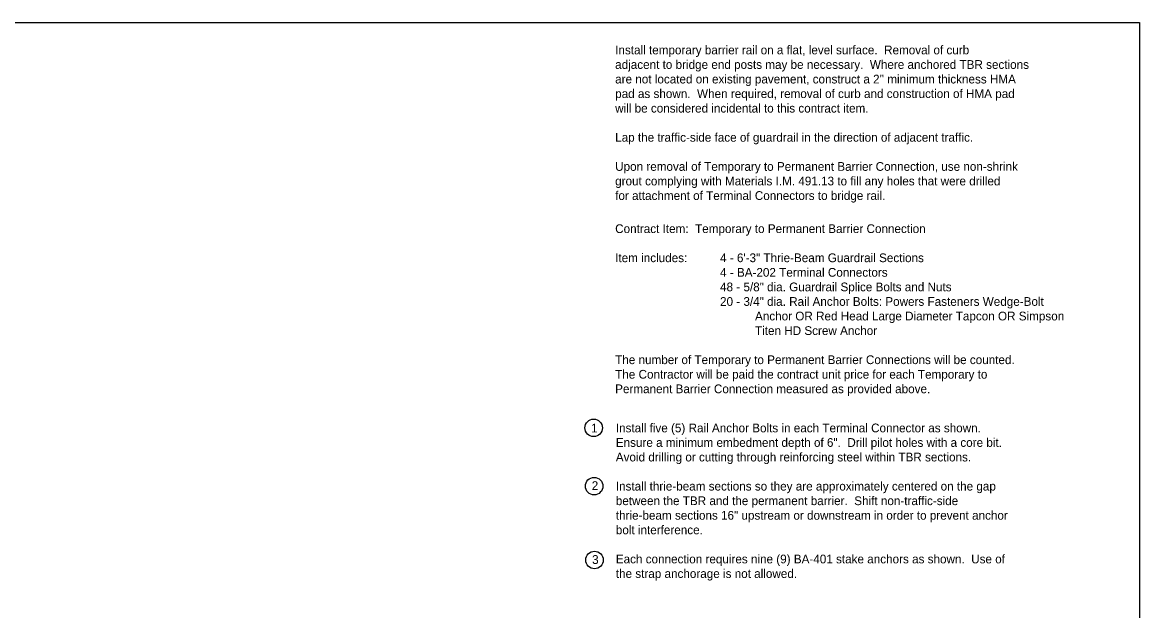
# Model space of a CAD drawing. Extents: x 10028 to 81668, y 3581 to 11018.
# Drawn here: x 14950 to 16868, y 8934 to 9944 of the extents above; entities that cross this region are included whole.
import ezdxf

# ---------------------------------------------------------------- set-up
doc = ezdxf.new("R2010")
doc.units = 0
for name, color, linetype in [('dsnTextTabulation', 7, 'Continuous'), ('Level 9', 7, 'Continuous'), ('SheetBorder', 7, 'Continuous')]:
    doc.layers.add(name, color=color, linetype=linetype)

msp = doc.modelspace()

# ---------------------------------------------------------------- linework, layer by layer
at = {"layer": 'dsnTextTabulation'}
for centre in [(15930.5, 9247.8), (15931.3, 9147.8), (15931.9, 9021)]:
    msp.add_circle(centre, 15, dxfattribs=at)
at = {"layer": 'SheetBorder'}
msp.add_lwpolyline([(13732.5, 9944), (16867.5, 9944), (16867.5, 7924), (13732.5, 7924)], close=True, dxfattribs=at)

# ---------------------------------------------------------------- texts
at = {"layer": 'dsnTextTabulation'}
for s, p in [('1', (15926.1, 9239.9)), ('2', (15927.1, 9141)), ('3', (15927.7, 9014.2))]:
    msp.add_text(s, height=15.2, dxfattribs=at).set_placement(p)
at = {"layer": 'Level 9'}
for s, p in [('Install temporary barrier rail on a flat, level surface.  Removal of curb ', (15967.4, 9889.1)), ('adjacent to bridge end posts may be necessary.  Where anchored TBR sections ', (15967.4, 9864.1)), ("are not located on existing pavement, construct a 2'' minimum thickness HMA ", (15967.4, 9839.1)), ('pad as shown.  When required, removal of curb and construction of HMA pad ', (15967.4, 9814.1)), ('will be considered incidental to this contract item.', (15967.4, 9789.1)), ('Lap the traffic-side face of guardrail in the direction of adjacent traffic.', (15967.4, 9739.1)), ('Upon removal of Temporary to Permanent Barrier Connection, use non-shrink ', (15967.4, 9689.1)), ('grout complying with Materials I.M. 491.13 to fill any holes that were drilled ', (15967.4, 9664.1)), ('for attachment of Terminal Connectors to bridge rail.', (15967.4, 9639.1)), ('Contract Item:  Temporary to Permanent Barrier Connection', (15967.4, 9582.3)), ('Item includes:', (15967.4, 9532.3)), ('4 - 6\'-3" Thrie-Beam Guardrail Sections', (16147.4, 9532.3)), ('4 - BA-202 Terminal Connectors', (16147.4, 9507.3)), ('48 - 5/8" dia. Guardrail Splice Bolts and Nuts', (16147.4, 9482.3)), ('20 - 3/4" dia. Rail Anchor Bolts: Powers Fasteners Wedge-Bolt', (16147.4, 9457.3)), ('Anchor OR Red Head Large Diameter Tapcon OR Simpson', (16207.4, 9432.3)), ('Titen HD Screw Anchor', (16207.4, 9407.3)), ('The number of Temporary to Permanent Barrier Connections will be counted.  ', (15967.4, 9357.3)), ('The Contractor will be paid the contract unit price for each Temporary to ', (15967.4, 9332.3)), ('Permanent Barrier Connection measured as provided above.', (15967.4, 9307.3)), ('Install five (5) Rail Anchor Bolts in each Terminal Connector as shown.  ', (15968.5, 9240.2)), ('Ensure a minimum embedment depth of 6".  Drill pilot holes with a core bit.  ', (15968.5, 9215.2)), ('Avoid drilling or cutting through reinforcing steel within TBR sections.', (15968.5, 9190.2)), ('Install thrie-beam sections so they are approximately centered on the gap ', (15968.5, 9140.2)), ('between the TBR and the permanent barrier.  Shift non-traffic-side ', (15968.5, 9115.2)), ('thrie-beam sections 16" upstream or downstream in order to prevent anchor ', (15968.5, 9090.2)), ('bolt interference.', (15968.5, 9065.2)), ('Each connection requires nine (9) BA-401 stake anchors as shown.  Use of ', (15968.5, 9015.2)), ('the strap anchorage is not allowed.', (15968.5, 8990.2))]:
    msp.add_text(s, height=15, dxfattribs=at).set_placement(p)

doc.saveas('drawing.dxf')
